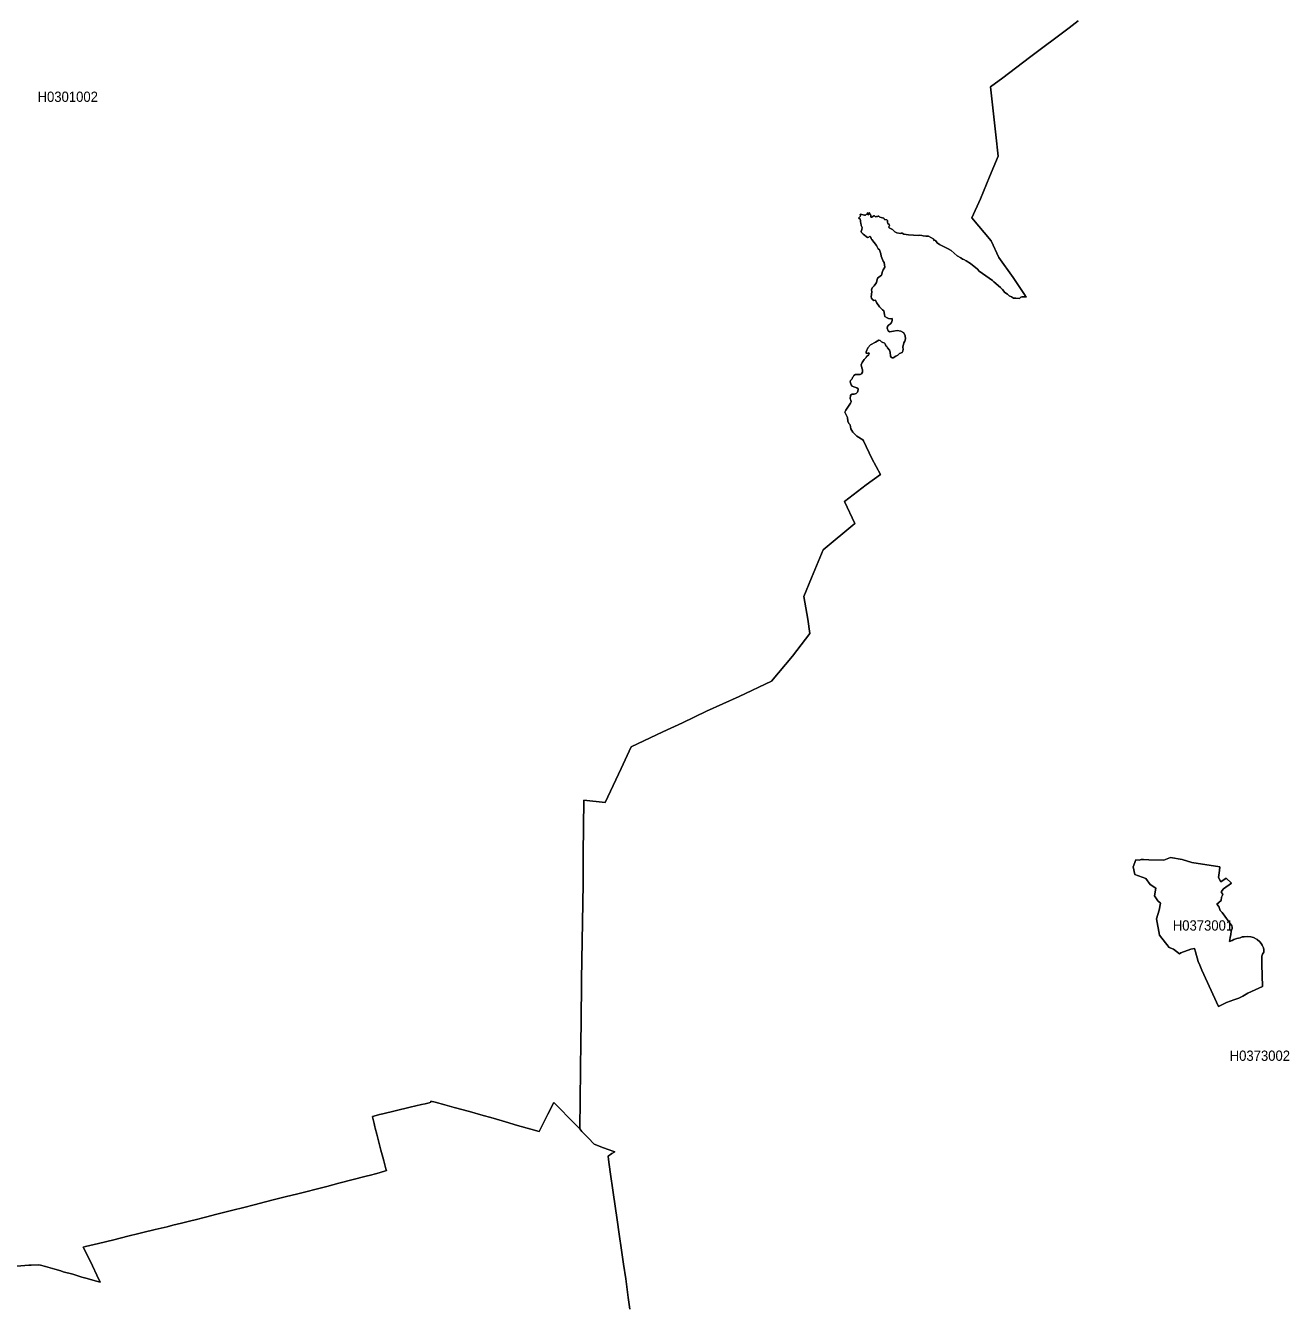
# Model space of a CAD drawing. Extents: x 369010 to 739155, y 6377141 to 6616555.
# Drawn here: x 386598 to 398878, y 6463211 to 6475665 of the extents above; entities that cross this region are included whole.
import ezdxf
from ezdxf.enums import TextEntityAlignment as Align

# ---------------------------------------------------------------- set-up
doc = ezdxf.new("R2010")
doc.units = 0
doc.header["$LTSCALE"] = 40
doc.layers.add('1', color=7, linetype='Continuous', lineweight=13)
doc.layers.add('2', color=7, linetype='Continuous')

msp = doc.modelspace()

# ---------------------------------------------------------------- linework, layer by layer
at = {"layer": '1'}
for points in [[(396826.79, 6475711.69), (396737.92, 6475644.66), (396353.29, 6475354.87), (396092.62, 6475157.75), (395974.78, 6475071.03), (396025.09, 6474605.46), (396050.25, 6474396.1), (395963.53, 6474194.68), (395876.14, 6473984), (395792.39, 6473796.98), (395980.08, 6473575.04), (396055.71, 6473411.35), (396193.74, 6473218.04), (396312.74, 6473043.77), (396322.83, 6473029.37), (396279.64, 6473031.19), (396269.71, 6473026.23), (396257.63, 6473014.97), (396219.23, 6473018.12), (396197.71, 6473016.46), (396179.51, 6473030.2), (396155.51, 6473039.96), (396139.29, 6473055.52), (396112.98, 6473071.41), (396092.29, 6473100.21), (396072.26, 6473121.72), (396006.39, 6473176.34), (395994.81, 6473189.25), (395864.72, 6473278.95), (395848.17, 6473297.49), (395778.49, 6473355.74), (395739.27, 6473381.07), (395714.94, 6473391.66), (395700.54, 6473396.46), (395687.46, 6473408.21), (395650.89, 6473429.39), (395591.97, 6473480.53), (395562.34, 6473497.25), (395479.1, 6473539.29), (395455.76, 6473555.34), (395440.04, 6473579.17), (395431.26, 6473581.16), (395424.31, 6473576.86), (395422.16, 6473579.51), (395424.48, 6473589.44), (395394.85, 6473607.64), (395370.69, 6473618.4), (395344.71, 6473620.88), (395320.38, 6473621.54), (395306.81, 6473626.51), (395287.94, 6473628.49), (395275.53, 6473626.34), (395176.39, 6473631.47), (395132.7, 6473639.75), (395115.15, 6473649.84), (395106.38, 6473649.35), (395099.26, 6473645.71), (395063.85, 6473653.15), (395043.32, 6473662.42), (395021.97, 6473683.61), (395003.27, 6473694.03), (394990.36, 6473701.15), (394986.39, 6473709.59), (394993.18, 6473723.99), (394990.86, 6473732.1), (394977.62, 6473743.35), (394972.16, 6473755.93), (394972.16, 6473771.16), (394967.19, 6473779.1), (394945.01, 6473781.59), (394936.24, 6473794), (394899, 6473805.75), (394889.57, 6473813.2), (394883.12, 6473813.53), (394875.67, 6473809.72), (394865.24, 6473811.38), (394856.63, 6473808.89), (394847.7, 6473815.84), (394840.58, 6473817.5), (394820.89, 6473804.26), (394812.94, 6473805.58), (394809.8, 6473810.71), (394812.61, 6473821.8), (394808.8, 6473830.57), (394800.86, 6473836.86), (394799.7, 6473845.64), (394794.07, 6473847.13), (394789.27, 6473842.66), (394791.92, 6473829.75)], [(395994.81, 6473189.25), (396006.39, 6473176.34), (396072.26, 6473121.72), (396092.29, 6473100.21), (396112.98, 6473071.41), (396139.29, 6473055.52), (396155.51, 6473039.96), (396179.51, 6473030.2), (396197.71, 6473016.46), (396219.23, 6473018.12), (396257.63, 6473014.97), (396269.71, 6473026.23), (396279.64, 6473031.19), (396322.83, 6473029.37), (396312.74, 6473043.77), (396193.74, 6473218.04), (396055.71, 6473411.35), (395980.08, 6473575.04), (395792.39, 6473796.98), (395876.14, 6473984), (395963.53, 6474194.68), (396050.25, 6474396.1), (396025.09, 6474605.46), (395974.78, 6475071.03), (396092.62, 6475157.75), (396353.29, 6475354.87), (396737.92, 6475644.66), (396826.79, 6475711.69)], [(394947, 6473317.18), (394941.54, 6473362.86), (394931.77, 6473376.93), (394912.91, 6473423.77), (394908.27, 6473447.6), (394897.18, 6473485.5), (394883.12, 6473497.75), (394865.57, 6473528.53), (394819.89, 6473585.79), (394815.59, 6473592.58), (394812.94, 6473611.28), (394802.18, 6473618.4), (394793.25, 6473610.29), (394778.19, 6473607.97), (394735.65, 6473640.08), (394720.59, 6473655.31), (394717.45, 6473666.56), (394724.07, 6473685.76), (394725.56, 6473702.64), (394718.6, 6473724.16), (394714.96, 6473749.81), (394709.5, 6473756.93), (394711.32, 6473767.35), (394706.36, 6473788.04), (394695.93, 6473792.84), (394695.77, 6473798.3), (394709.34, 6473810.38), (394710, 6473817.17), (394707.02, 6473829.75), (394711.98, 6473833.06), (394749.22, 6473824.12), (394760.31, 6473823.29), (394765.11, 6473829.09), (394775.7, 6473833.72), (394778.68, 6473844.97), (394781.83, 6473845.64), (394783.15, 6473830.41), (394788.28, 6473826.77), (394791.92, 6473829.75), (394789.27, 6473842.66), (394794.07, 6473847.13), (394799.7, 6473845.64), (394800.86, 6473836.86), (394808.8, 6473830.57), (394812.61, 6473821.8), (394809.8, 6473810.71), (394812.94, 6473805.58), (394820.89, 6473804.26), (394840.58, 6473817.5), (394847.7, 6473815.84), (394856.63, 6473808.89), (394865.24, 6473811.38), (394875.67, 6473809.72), (394883.12, 6473813.53), (394889.57, 6473813.2), (394899, 6473805.75), (394936.24, 6473794), (394945.01, 6473781.59), (394967.19, 6473779.1), (394972.16, 6473771.16), (394972.16, 6473755.93), (394977.62, 6473743.35), (394990.86, 6473732.1), (394993.18, 6473723.99), (394986.39, 6473709.59), (394990.36, 6473701.15), (395003.27, 6473694.03), (395021.97, 6473683.61), (395043.32, 6473662.42), (395063.85, 6473653.15), (395099.26, 6473645.71), (395106.38, 6473649.35), (395115.15, 6473649.84), (395132.7, 6473639.75), (395176.39, 6473631.47), (395275.53, 6473626.34), (395287.94, 6473628.49), (395306.81, 6473626.51), (395320.38, 6473621.54), (395344.71, 6473620.88), (395370.69, 6473618.4), (395394.85, 6473607.64), (395424.48, 6473589.44), (395422.16, 6473579.51), (395424.31, 6473576.86), (395431.26, 6473581.16), (395440.04, 6473579.17), (395455.76, 6473555.34), (395479.1, 6473539.29), (395562.34, 6473497.25), (395591.97, 6473480.53), (395650.89, 6473429.39), (395687.46, 6473408.21), (395700.54, 6473396.46), (395714.94, 6473391.66), (395739.27, 6473381.07), (395778.49, 6473355.74), (395848.17, 6473297.49), (395864.72, 6473278.95), (395994.81, 6473189.25)], [(394791.92, 6473829.75), (394788.28, 6473826.77), (394783.15, 6473830.41), (394781.83, 6473845.64), (394778.68, 6473844.97), (394775.7, 6473833.72), (394765.11, 6473829.09), (394760.31, 6473823.29), (394749.22, 6473824.12), (394711.98, 6473833.06), (394707.02, 6473829.75), (394710, 6473817.17), (394709.34, 6473810.38), (394695.77, 6473798.3), (394695.93, 6473792.84), (394706.36, 6473788.04), (394711.32, 6473767.35), (394709.5, 6473756.93), (394714.96, 6473749.81), (394718.6, 6473724.16), (394725.56, 6473702.64), (394724.07, 6473685.76), (394717.45, 6473666.56), (394720.59, 6473655.31), (394735.65, 6473640.08), (394778.19, 6473607.97), (394793.25, 6473610.29), (394802.18, 6473618.4), (394812.94, 6473611.28), (394815.59, 6473592.58), (394819.89, 6473585.79), (394865.57, 6473528.53), (394883.12, 6473497.75), (394897.18, 6473485.5), (394908.27, 6473447.6), (394912.91, 6473423.77), (394931.77, 6473376.93), (394941.54, 6473362.86), (394947, 6473317.18), (394931.61, 6473292.02), (394924.66, 6473277.46), (394915.39, 6473242.21), (394876.66, 6473211.59), (394865.41, 6473169.88), (394858.62, 6473161.11), (394844.39, 6473137.11), (394823.7, 6473117.91), (394819.23, 6473099.54), (394821.38, 6473079.19), (394815.92, 6473029.04), (394818.24, 6473016.46), (394827.84, 6473003.55), (394841.57, 6472995.11), (394855.15, 6472997.26), (394866.4, 6472973.76), (394894.54, 6472931.89), (394925.15, 6472902.92), (394938.39, 6472894.65), (394942.86, 6472859.56), (394947.99, 6472838.71), (394971.33, 6472824.81), (394984.07, 6472819.35), (395000.95, 6472816.7), (395018.33, 6472818.35), (395019.33, 6472801.14), (395011.71, 6472781.11), (395001.95, 6472767.21), (394982.42, 6472753.81), (394973.81, 6472742.06), (394970.5, 6472725.5), (394978.45, 6472698.69), (394993.18, 6472691.41), (395031.24, 6472696.54), (395066.66, 6472701.51), (395103.24, 6472695.38), (395132.86, 6472679.99), (395143.95, 6472651.86), (395147.26, 6472622.06), (395141.47, 6472600.22), (395131.21, 6472582.34), (395123.26, 6472541.46), (395125.08, 6472521.93), (395123.26, 6472502.57), (395114.99, 6472489.83), (395088.67, 6472478.74), (395072.95, 6472463.18), (395054.25, 6472453.42), (395029.42, 6472438.02), (395018, 6472436.37), (395008.24, 6472443.32), (395001.45, 6472454.24), (394998.31, 6472492.97), (394991.85, 6472512), (394973.81, 6472534.84), (394966.36, 6472546.76), (394957.92, 6472554.21), (394951.3, 6472572.25), (394940.21, 6472581.85), (394927.97, 6472587.47), (394914.56, 6472592.77)], [(394669.62, 6472091.96), (394681.37, 6472104.7), (394689.31, 6472125.06), (394686.83, 6472136.14), (394674.08, 6472146.74), (394646.94, 6472155.34), (394631.05, 6472161.96), (394618.97, 6472175.04), (394610.86, 6472204.17), (394615.16, 6472216.25), (394629.23, 6472231.97), (394633.7, 6472246.04), (394640.16, 6472253.98), (394644.96, 6472266.89), (394661.01, 6472275.66), (394676.9, 6472274.18), (394708.84, 6472275.66), (394719.1, 6472280.96), (394729.69, 6472299.5), (394729.53, 6472319.52), (394723.4, 6472339.55), (394718.6, 6472369.84), (394727.71, 6472390.69), (394746.24, 6472420.81), (394757, 6472432.23), (394766.44, 6472439.68), (394770.24, 6472449.11), (394787.95, 6472462.52), (394796.23, 6472477.58), (394789.27, 6472485.03), (394777.03, 6472481.06), (394766.93, 6472482.38), (394765.94, 6472496.78), (394782.99, 6472534.68), (394809.3, 6472565.13), (394856.47, 6472588.63), (394887.92, 6472608.66), (394903.64, 6472606.34), (394914.56, 6472592.77), (394927.97, 6472587.47), (394940.21, 6472581.85), (394951.3, 6472572.25), (394957.92, 6472554.21), (394966.36, 6472546.76), (394973.81, 6472534.84), (394991.85, 6472512), (394998.31, 6472492.97), (395001.45, 6472454.24), (395008.24, 6472443.32), (395018, 6472436.37), (395029.42, 6472438.02), (395054.25, 6472453.42), (395072.95, 6472463.18), (395088.67, 6472478.74), (395114.99, 6472489.83), (395123.26, 6472502.57), (395125.08, 6472521.93), (395123.26, 6472541.46), (395131.21, 6472582.34), (395141.47, 6472600.22), (395147.26, 6472622.06), (395143.95, 6472651.86), (395132.86, 6472679.99), (395103.24, 6472695.38), (395066.66, 6472701.51), (395031.24, 6472696.54), (394993.18, 6472691.41), (394978.45, 6472698.69), (394970.5, 6472725.5), (394973.81, 6472742.06), (394982.42, 6472753.81), (395001.95, 6472767.21), (395011.71, 6472781.11), (395019.33, 6472801.14), (395018.33, 6472818.35), (395000.95, 6472816.7), (394984.07, 6472819.35), (394971.33, 6472824.81), (394947.99, 6472838.71), (394942.86, 6472859.56), (394938.39, 6472894.65), (394925.15, 6472902.92), (394894.54, 6472931.89), (394866.4, 6472973.76), (394855.15, 6472997.26), (394841.57, 6472995.11), (394827.84, 6473003.55), (394818.24, 6473016.46), (394815.92, 6473029.04), (394821.38, 6473079.19), (394819.23, 6473099.54), (394823.7, 6473117.91), (394844.39, 6473137.11), (394858.62, 6473161.11), (394865.41, 6473169.88), (394876.66, 6473211.59), (394915.39, 6473242.21), (394924.66, 6473277.46), (394931.61, 6473292.02), (394947, 6473317.18)], [(394914.56, 6472592.77), (394903.64, 6472606.34), (394887.92, 6472608.66), (394856.47, 6472588.63), (394809.3, 6472565.13), (394782.99, 6472534.68), (394765.94, 6472496.78), (394766.93, 6472482.38), (394777.03, 6472481.06), (394789.27, 6472485.03), (394796.23, 6472477.58), (394787.95, 6472462.52), (394770.24, 6472449.11), (394766.44, 6472439.68), (394757, 6472432.23), (394746.24, 6472420.81), (394727.71, 6472390.69), (394718.6, 6472369.84), (394723.4, 6472339.55), (394729.53, 6472319.52), (394729.69, 6472299.5), (394719.1, 6472280.96), (394708.84, 6472275.66), (394676.9, 6472274.18), (394661.01, 6472275.66), (394644.96, 6472266.89), (394640.16, 6472253.98), (394633.7, 6472246.04), (394629.23, 6472231.97), (394615.16, 6472216.25), (394610.86, 6472204.17), (394618.97, 6472175.04), (394631.05, 6472161.96), (394646.94, 6472155.34), (394674.08, 6472146.74), (394686.83, 6472136.14), (394689.31, 6472125.06), (394681.37, 6472104.7), (394669.62, 6472091.96), (394650.91, 6472084.01), (394630.39, 6472085.5), (394613.68, 6472075.9), (394612.85, 6472061.01), (394609.54, 6472049.92), (394609.04, 6472038.66), (394618.64, 6472026.25), (394619.96, 6472010.53), (394614.17, 6471996.29), (394569.32, 6471929.93), (394560.22, 6471908.25), (394584.55, 6471856.28), (394589.01, 6471821.52), (394598.95, 6471800.67), (394609.7, 6471787.76), (394616.16, 6471746.22), (394636.02, 6471716.59), (394674.75, 6471677.7), (394733, 6471639.8), (394739.13, 6471630.36), (394822.54, 6471460.56), (394904.47, 6471303.66), (394765.61, 6471202.54), (394556.08, 6471041.5), (394655.55, 6470826.84), (394349.53, 6470573.13), (394235.99, 6470299.22), (394159.53, 6470118.82), (394198.26, 6469898.7), (394220.11, 6469758.68), (394049.14, 6469539.72), (393846.73, 6469296.92), (393532.77, 6469146.81), (393215.83, 6469003.98), (392980.15, 6468889.95), (392790.48, 6468802.4), (392480.83, 6468657.75), (392385.33, 6468448.05), (392230.09, 6468118.37), (392021.88, 6468138.56), (392015.59, 6467619.21), (392014.77, 6467326.76), (392001.36, 6466395.97), (391996.06, 6465965.49), (391992.59, 6465800.49), (391982, 6464947.64), (392004.34, 6464920.17), (392064.75, 6464858.27), (392123.17, 6464797.37), (392150.31, 6464786.44), (392187.22, 6464772.38), (392247.63, 6464750.03), (392322.11, 6464723.72), (392295.63, 6464707), (392257.89, 6464681.84), (392262.53, 6464647.42), (392279.74, 6464528.75), (392308.7, 6464327.34), (392327.57, 6464194.93), (392347.76, 6464061.04), (392366.96, 6463922.84)], [(389320.86, 6464334.78), (389421.98, 6464360.27), (389524.92, 6464387.08), (389643.09, 6464417.2), (389779.47, 6464452.29), (389895.82, 6464482.08), (389963.67, 6464500.45), (389984.36, 6464506.08), (389999.26, 6464509.56), (390032.19, 6464519.32), (390104.85, 6464539.68), (390099.88, 6464556.06), (390079.2, 6464635.17), (390069.6, 6464670.92), (390051.06, 6464739.94), (390036.66, 6464790.42), (390009.85, 6464892.86), (389995.62, 6464952.44), (389992.97, 6464966.51), (389985.02, 6464997.3), (389978.4, 6465023.61), (389969.3, 6465062.17), (389968.81, 6465066.15), (389981.88, 6465069.95), (390036, 6465085.01), (390069.27, 6465092.79), (390190.25, 6465120.93), (390333.74, 6465155.02), (390445.46, 6465182.33), (390479.39, 6465189.78), (390518.94, 6465199.38), (390536.15, 6465204.67), (390536.65, 6465210.46), (390536.65, 6465215.26), (390576.37, 6465206.16), (390671.87, 6465179.35), (390761.4, 6465154.36), (390851.44, 6465129.2), (390934.85, 6465106.86), (391023.07, 6465082.2), (391140.9, 6465048.93), (391261.06, 6465014.51), (391379.4, 6464979.92), (391506.17, 6464943.01), (391586.94, 6464920.67), (391607.29, 6464959.4), (391659.26, 6465063.33), (391671.18, 6465087.5), (391730.6, 6465201.36), (391736.72, 6465195.24), (391759.56, 6465171.57), (391807.89, 6465122.75), (391864.49, 6465064.82), (391982, 6464947.64), (391992.59, 6465800.49), (391996.06, 6465965.49), (392001.36, 6466395.97), (392014.77, 6467326.76), (392015.59, 6467619.21), (392021.88, 6468138.56), (392230.09, 6468118.37), (392385.33, 6468448.05), (392480.83, 6468657.75), (392790.48, 6468802.4), (392980.15, 6468889.95), (393215.83, 6469003.98), (393532.77, 6469146.81), (393846.73, 6469296.92), (394049.14, 6469539.72), (394220.11, 6469758.68), (394198.26, 6469898.7), (394159.53, 6470118.82), (394235.99, 6470299.22), (394349.53, 6470573.13), (394655.55, 6470826.84), (394556.08, 6471041.5), (394765.61, 6471202.54), (394904.47, 6471303.66), (394822.54, 6471460.56), (394739.13, 6471630.36), (394733, 6471639.8), (394674.75, 6471677.7), (394636.02, 6471716.59), (394616.16, 6471746.22), (394609.7, 6471787.76), (394598.95, 6471800.67), (394589.01, 6471821.52), (394584.55, 6471856.28), (394560.22, 6471908.25), (394569.32, 6471929.93), (394614.17, 6471996.29), (394619.96, 6472010.53), (394618.64, 6472026.25), (394609.04, 6472038.66), (394609.54, 6472049.92), (394612.85, 6472061.01), (394613.68, 6472075.9), (394630.39, 6472085.5), (394650.91, 6472084.01), (394669.62, 6472091.96)], [(391864.49, 6465064.82), (391807.89, 6465122.75), (391759.56, 6465171.57), (391736.72, 6465195.24), (391730.6, 6465201.36), (391671.18, 6465087.5), (391659.26, 6465063.33), (391607.29, 6464959.4), (391586.94, 6464920.67), (391506.17, 6464943.01), (391379.4, 6464979.92), (391261.06, 6465014.51), (391140.9, 6465048.93), (391023.07, 6465082.2), (390934.85, 6465106.86), (390851.44, 6465129.2), (390761.4, 6465154.36), (390671.87, 6465179.35), (390576.37, 6465206.16), (390536.65, 6465215.26), (390536.65, 6465210.46), (390536.15, 6465204.67), (390518.94, 6465199.38), (390479.39, 6465189.78), (390445.46, 6465182.33), (390333.74, 6465155.02), (390190.25, 6465120.93), (390069.27, 6465092.79), (390036, 6465085.01), (389981.88, 6465069.95), (389968.81, 6465066.15), (389969.3, 6465062.17), (389978.4, 6465023.61), (389985.02, 6464997.3), (389992.97, 6464966.51), (389995.62, 6464952.44), (390009.85, 6464892.86), (390036.66, 6464790.42), (390051.06, 6464739.94), (390069.6, 6464670.92), (390079.2, 6464635.17), (390099.88, 6464556.06), (390104.85, 6464539.68), (390032.19, 6464519.32), (389999.26, 6464509.56), (389984.36, 6464506.08), (389963.67, 6464500.45), (389895.82, 6464482.08), (389779.47, 6464452.29), (389643.09, 6464417.2), (389524.92, 6464387.08), (389421.98, 6464360.27), (389320.86, 6464334.78), (389230.99, 6464312.11), (389133.67, 6464287.61), (389017.98, 6464258.15), (388928.28, 6464235.81), (388817.89, 6464207.68), (388717.93, 6464181.86), (388611.51, 6464154.22), (388509.56, 6464128.4), (388444.02, 6464112.18), (388360.11, 6464091.66), (388320.22, 6464081.89), (388270.07, 6464068.32), (388178.71, 6464046.48), (388111.52, 6464030.09), (388028.11, 6464009.07), (387972.66, 6463995), (387855.48, 6463967.53), (387738.31, 6463939.06), (387699.08, 6463929.46), (387590.84, 6463903.15), (387456.29, 6463868.89), (387304.69, 6463832.97), (387179.07, 6463802.69), (387158.38, 6463797.89), (387195.29, 6463722.58), (387246.93, 6463616.5), (387289.79, 6463525.3), (387323.72, 6463455.46), (387273.57, 6463469.86), (387195.12, 6463492.53), (387145.8, 6463506.1), (387055.77, 6463532.42), (386963.91, 6463557.74), (386939.75, 6463564.86), (386882.98, 6463581.08), (386792.29, 6463606.9), (386741.31, 6463620.96), (386724.76, 6463626.26), (386653.1, 6463621.79), (386629.27, 6463620.47), (386473.69, 6463609.05)], [(392470.56, 6463192.97), (392454.18, 6463306.18), (392429.19, 6463490.05), (392409.49, 6463632.38), (392389.8, 6463767.44), (392366.96, 6463922.84), (392347.76, 6464061.04), (392327.57, 6464194.93), (392308.7, 6464327.34), (392279.74, 6464528.75), (392262.53, 6464647.42), (392257.89, 6464681.84), (392295.63, 6464707), (392322.11, 6464723.72), (392247.63, 6464750.03), (392187.22, 6464772.38), (392150.31, 6464786.44), (392123.17, 6464797.37), (392064.75, 6464858.27), (392004.34, 6464920.17), (391982, 6464947.64), (391864.49, 6465064.82)], [(386473.69, 6463609.05), (386629.27, 6463620.47), (386653.1, 6463621.79), (386724.76, 6463626.26), (386741.31, 6463620.96), (386792.29, 6463606.9), (386882.98, 6463581.08), (386939.75, 6463564.86), (386963.91, 6463557.74), (387055.77, 6463532.42), (387145.8, 6463506.1), (387195.12, 6463492.53), (387273.57, 6463469.86), (387323.72, 6463455.46), (387289.79, 6463525.3), (387246.93, 6463616.5), (387195.29, 6463722.58), (387158.38, 6463797.89), (387179.07, 6463802.69), (387304.69, 6463832.97), (387456.29, 6463868.89), (387590.84, 6463903.15), (387699.08, 6463929.46), (387738.31, 6463939.06), (387855.48, 6463967.53), (387972.66, 6463995), (388028.11, 6464009.07), (388111.52, 6464030.09), (388178.71, 6464046.48), (388270.07, 6464068.32), (388320.22, 6464081.89), (388360.11, 6464091.66), (388444.02, 6464112.18), (388509.56, 6464128.4), (388611.51, 6464154.22), (388717.93, 6464181.86), (388817.89, 6464207.68), (388928.28, 6464235.81), (389017.98, 6464258.15), (389133.67, 6464287.61), (389230.99, 6464312.11), (389320.86, 6464334.78)], [(392366.96, 6463922.84), (392389.8, 6463767.44), (392409.49, 6463632.38), (392429.19, 6463490.05), (392454.18, 6463306.18), (392470.56, 6463192.97)]]:
    msp.add_lwpolyline(points, dxfattribs=at)
for points in [[(398322.95, 6466776.96), (398295.48, 6466767.69), (398304.25, 6466803.94), (398310.37, 6466833.89), (398312.85, 6466865.17), (398321.63, 6466892.65), (398322.95, 6466905.06), (398317.99, 6466918.8), (398225.63, 6467047.39), (398206.93, 6467068.58), (398193.2, 6467104.82), (398174.33, 6467128.32), (398216.86, 6467164.57), (398218.02, 6467195.85), (398233.08, 6467224.48), (398214.38, 6467249.47), (398238.05, 6467279.43), (398314.84, 6467331.73), (398264.2, 6467381.71), (398211.57, 6467346.29), (398190.38, 6467387.34), (398198.16, 6467456.35), (398201.64, 6467493.26), (397929.22, 6467534.64), (397836.7, 6467561.95), (397722.34, 6467582.47), (397657.62, 6467557.97), (397512.64, 6467559.79), (397462, 6467564.43), (397437.34, 6467563.43), (397418.97, 6467557.48), (397385.54, 6467559.96), (397359.88, 6467491.77), (397377.1, 6467415.81), (397482.69, 6467379.23), (397525.06, 6467320.48), (397581.99, 6467283.9), (397568.91, 6467210.25), (397601.35, 6467160.27), (397625.19, 6467140.41), (397613.93, 6467072.05), (397586.79, 6466985.66), (397615.09, 6466828.43), (397711.41, 6466707.61), (397753.62, 6466692.55), (397811.05, 6466647.54), (397824.78, 6466657.47), (397919.62, 6466692.55), (397955.7, 6466698.68), (397965.79, 6466666.24), (397991.94, 6466571.4), (398007, 6466536.48), (398026.86, 6466486.67), (398189.06, 6466134.64), (398267.67, 6466174.53), (398338.84, 6466199.52), (398387.83, 6466214.58), (398426.39, 6466235.76), (398473.89, 6466263.24), (398617.38, 6466328.11), (398609.93, 6466541.61), (398609.93, 6466625.19), (398618.71, 6466644.72), (398629.8, 6466663.42), (398629.8, 6466688.42), (398627.31, 6466704.63), (398614.9, 6466729.63), (398604.97, 6466747), (398592.39, 6466762.06), (398564.92, 6466784.41), (398531.32, 6466805.76), (398503.85, 6466811.88), (398471.41, 6466814.36), (398440.13, 6466811.88), (398420.27, 6466810.72), (398400.24, 6466803.28), (398369.13, 6466795.66), (398339.17, 6466784.41)], [(398322.95, 6466776.96), (398339.17, 6466784.41), (398369.13, 6466795.66), (398400.24, 6466803.28), (398420.27, 6466810.72), (398440.13, 6466811.88), (398471.41, 6466814.36), (398503.85, 6466811.88), (398531.32, 6466805.76), (398564.92, 6466784.41), (398592.39, 6466762.06), (398604.97, 6466747), (398614.9, 6466729.63), (398627.31, 6466704.63), (398629.8, 6466688.42), (398629.8, 6466663.42), (398618.71, 6466644.72), (398609.93, 6466625.19), (398609.93, 6466541.61), (398617.38, 6466328.11), (398473.89, 6466263.24), (398426.39, 6466235.76), (398387.83, 6466214.58), (398338.84, 6466199.52), (398267.67, 6466174.53), (398189.06, 6466134.64), (398026.86, 6466486.67), (398007, 6466536.48), (397991.94, 6466571.4), (397965.79, 6466666.24), (397955.7, 6466698.68), (397919.62, 6466692.55), (397824.78, 6466657.47), (397811.05, 6466647.54), (397753.62, 6466692.55), (397711.41, 6466707.61), (397615.09, 6466828.43), (397586.79, 6466985.66), (397613.93, 6467072.05), (397625.19, 6467140.41), (397601.35, 6467160.27), (397568.91, 6467210.25), (397581.99, 6467283.9), (397525.06, 6467320.48), (397482.69, 6467379.23), (397377.1, 6467415.81), (397359.88, 6467491.77), (397385.54, 6467559.96), (397418.97, 6467557.48), (397437.34, 6467563.43), (397462, 6467564.43), (397512.64, 6467559.79), (397657.62, 6467557.97), (397722.34, 6467582.47), (397836.7, 6467561.95), (397929.22, 6467534.64), (398201.64, 6467493.26), (398198.16, 6467456.35), (398190.38, 6467387.34), (398211.57, 6467346.29), (398264.2, 6467381.71), (398314.84, 6467331.73), (398238.05, 6467279.43), (398214.38, 6467249.47), (398233.08, 6467224.48), (398218.02, 6467195.85), (398216.86, 6467164.57), (398174.33, 6467128.32), (398193.2, 6467104.82), (398206.93, 6467068.58), (398225.63, 6467047.39), (398317.99, 6466918.8), (398322.95, 6466905.06), (398321.63, 6466892.65), (398312.85, 6466865.17), (398310.37, 6466833.89), (398304.25, 6466803.94), (398295.48, 6466767.69)]]:
    msp.add_lwpolyline(points, close=True, dxfattribs=at)

# ---------------------------------------------------------------- texts
at = {"layer": '2', "width": 0.95}
for s, p in [('H0301002', (387007.46, 6474924.41)), ('H0373001', (398038.93, 6466872.4)), ('H0373002', (398591.73, 6465606.64))]:
    msp.add_text(s, height=100, dxfattribs=at).set_placement(p, align=Align.CENTER)

doc.saveas('drawing.dxf')
